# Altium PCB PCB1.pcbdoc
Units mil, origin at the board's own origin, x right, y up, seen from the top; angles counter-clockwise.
Board outline 2818.05 x 1914.09 mil, 2 copper layers (Top Layer, Bottom Layer), stack 62.206 mil thick; 39 components, 24 nets, 192 pads, 30 vias.
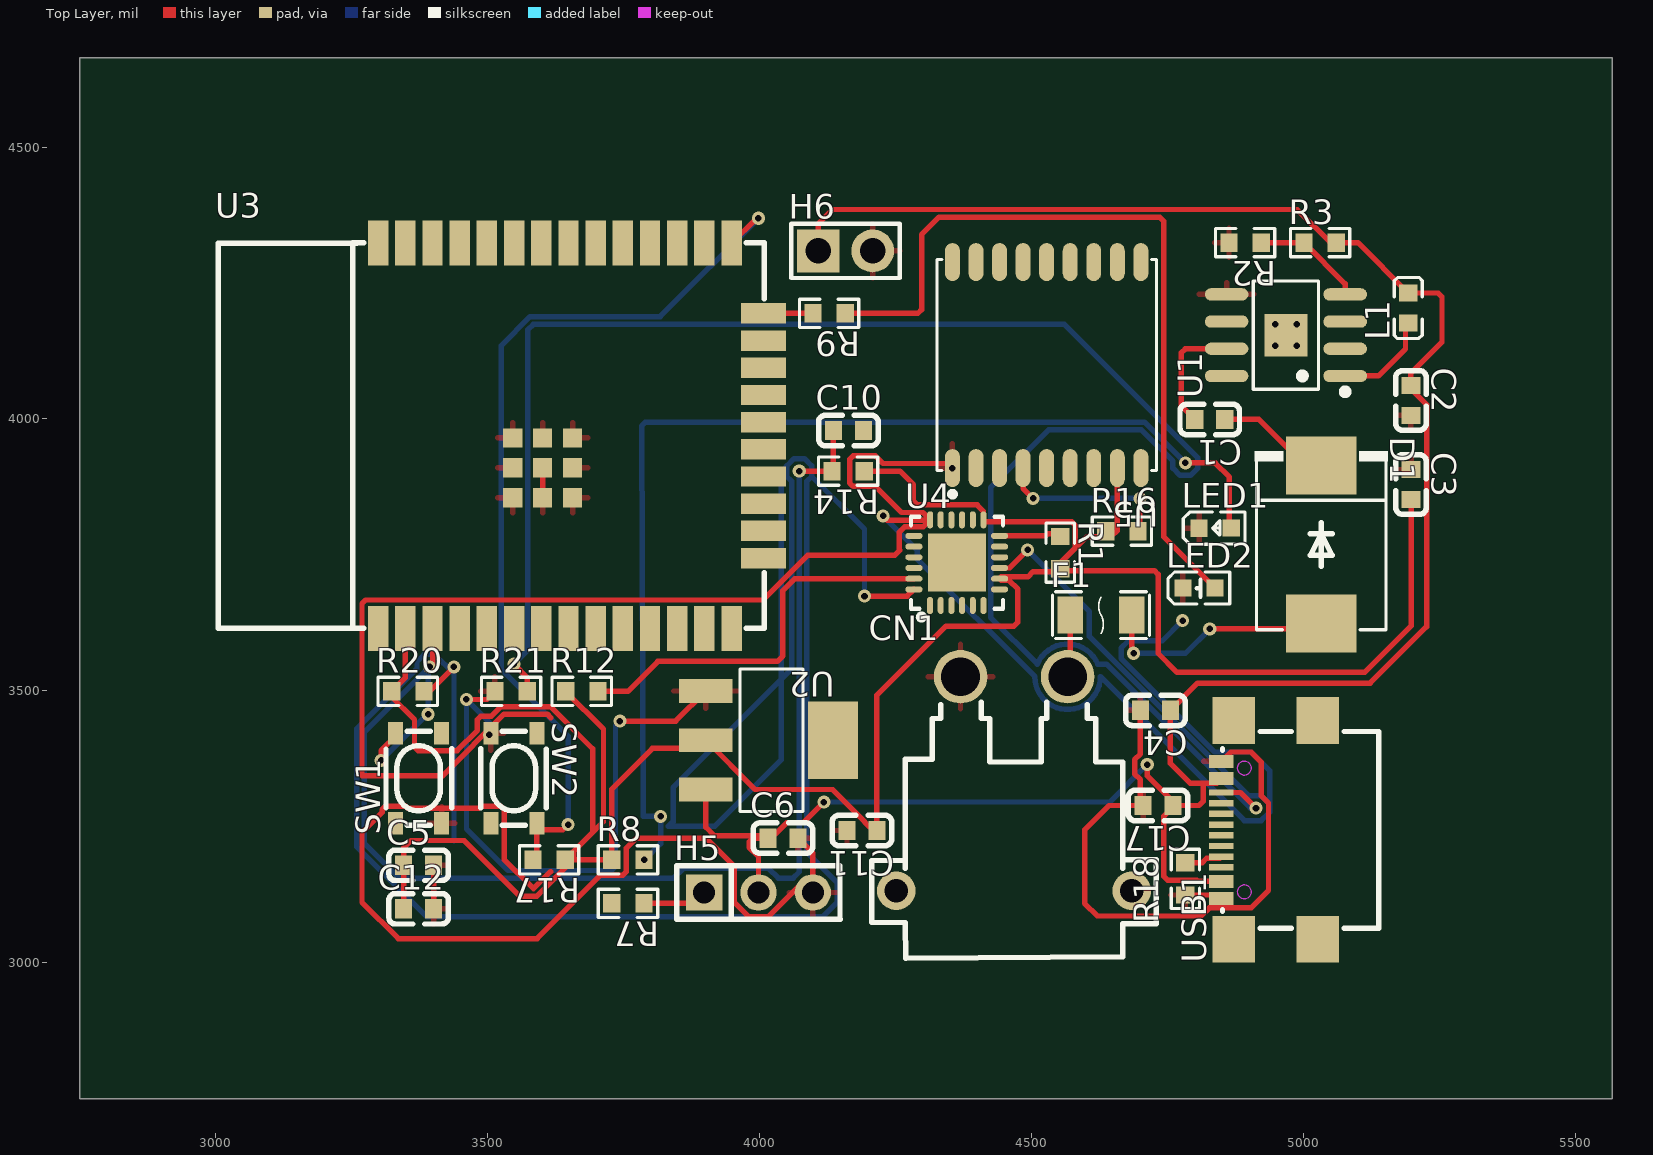
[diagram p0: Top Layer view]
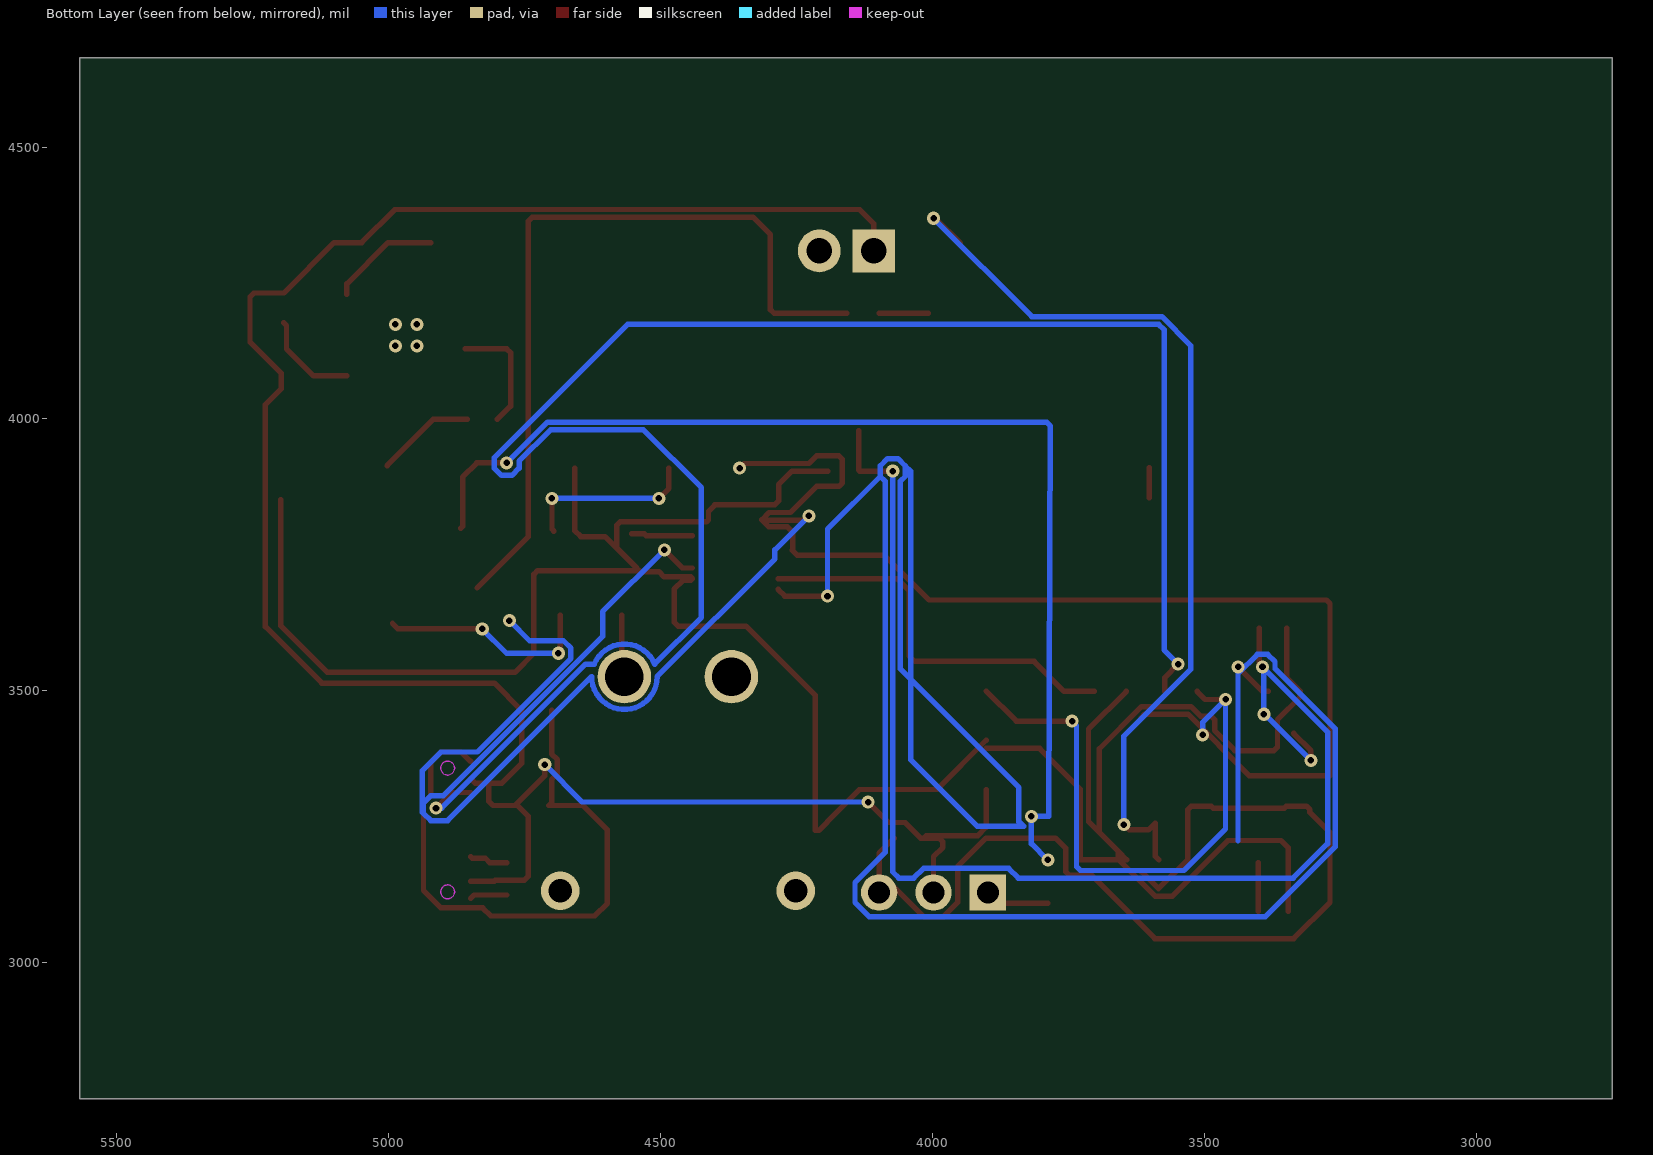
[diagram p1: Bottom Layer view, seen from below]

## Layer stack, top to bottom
Top Solder Mask Layer: solder mask 0.394, Dk 3.3
Top Layer: signal copper 1.379
Dielectric1: surface 59.449, FR4, Dk 4.5
Bottom Layer: signal copper 1.378
Bottom Solder Mask Layer: solder mask 0.394, Dk 3.3

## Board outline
5568.05,2750 2750,2750 2750,4664.09 5568.05,4664.09

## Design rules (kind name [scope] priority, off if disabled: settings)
BoardOutlineClearance copperThickness1oz [All] p0: genericclearance=10 ignorepadtopadclearanceinfootprint=FALSE except(0: Arc-SplitContinuation Track-SplitContinuation SMDPad-SplitContinuation THPad-SplitContinuation Via-SplitContinuation Fill-SplitContinuation Poly-SplitContinuation Region-SplitContinuation Text-SplitContinuation)
BoardOutlineClearance copperThickness2oz [All] p0: genericclearance=10 ignorepadtopadclearanceinfootprint=FALSE except(0: Arc-SplitContinuation Track-SplitContinuation SMDPad-SplitContinuation THPad-SplitContinuation Via-SplitContinuation Fill-SplitContinuation Poly-SplitContinuation Region-SplitContinuation Text-SplitContinuation)
BoardOutlineClearance otherClearance [All] p0: genericclearance=10 ignorepadtopadclearanceinfootprint=FALSE except(0: Arc-SplitContinuation Track-SplitContinuation SMDPad-SplitContinuation THPad-SplitContinuation Via-SplitContinuation Fill-SplitContinuation Poly-SplitContinuation Region-SplitContinuation Text-SplitContinuation)
Clearance copperThickness1oz [All] p1: gap=7 ignorepadtopadclearanceinfootprint=FALSE
Clearance copperThickness2oz [All] p1: gap=7 ignorepadtopadclearanceinfootprint=FALSE
Clearance otherClearance [All] p1: gap=7 ignorepadtopadclearanceinfootprint=FALSE
DiffPairsRouting differentialPair [All] p1: maxuncoupledlength=10 minlimit=6 maxlimit=Infinity mostfreqgap=6 toplayer_minwidth=5 toplayer_prefwidth=10 toplayer_maxwidth=100 bottomlayer_minwidth=5 bottomlayer_prefwidth=10 bottomlayer_maxwidth=100
PasteMaskExpansion pasteMaskExpansion [All] p1: expansion=0
PlaneConnect innerPlane [All] p1: planeconnectstyle=Relief reliefexpansion=20 reliefentries=4 reliefconductorwidth=10 reliefairgap=10
PolygonConnect copperRegion [All] p1: connectstyle=Relief reliefentries=4 reliefconductorwidth=10 polygonreliefangle="90 Angle" airgapwidth=10
RoutingVias viaSize [All] p1: viastyle="Through Hole" holewidth=12.0078 minholewidth=11.811 maxholewidth=248.0314 width=12.0078 minwidth=11.811 maxwidth=248.0314
SolderMaskExpansion solderMaskExpansion [All] p1: useseparateexpansions=TRUE expansion=2 expansionbottom=2
Width copperThickness1oz [All] p1: maxlimit=100 minlimit=5 preferedwidth=10
Width copperThickness2oz [All] p1: maxlimit=100 minlimit=8 preferedwidth=10

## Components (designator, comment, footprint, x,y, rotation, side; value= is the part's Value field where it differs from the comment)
C1 "" C0603 4828.05,3999.09 r180 top
C2 "" C0603 5198.05,4034.09 r270 top
C3 "" C0603 5198.27,3879.34 r270 top
C4 "" C0603 4728.05,3464.09 r180 top
C5 "" C0603 3373.05,3179.09 r0 top
C6 "" C0603 4043.05,3229.09 r0 top
C10 "" C0603 4163.4,3978.74 r0 top
C11 "" C0603 4188.4,3243.15 r180 top
C12 "" C0603 3373.05,3099.09 r0 top
C17 "" C0603 4733.05,3289.09 r180 top
CN1 "" CONN-TH_XT30PW-M 4468.05,3329.09 r0 top
D1 "" SMC_L6.9-W5.9-LS7.9-RD 5033.05,3769.09 r270 top
F1 "" F1206 4628.05,3639.09 r0 top
H5 "" HDR-TH_3P-P2.54-V-M_PZ254V-11-03P 3998.05,3129.09 r0 top
H6 "" HDR-TH_2P-P2.54-V-M 4158.05,4309.09 r0 top
L1 "" L0603 5193.05,4204.09 r90 top
LED1 "" LED0603-RD_RED 4838.05,3799.09 r0 top
LED2 "" LED0603-R-RD 4808.05,3689.09 r0 top
R1 "" R0603 4553.05,3754.09 r270 top
R2 "" R0603 4893.05,4324.09 r180 top
R3 "" R0603 5030.97,4324.34 r0 top
R7 "" R0603 3758.05,3109.09 r180 top
R8 "" R0603 3758.05,3189.09 r0 top
R9 "" R0603 4128.05,4194.09 r180 top
R12 "" R0603 3673.05,3499.09 r0 top
R14 "" R0603 4163.05,3904.09 r180 top
R16 "" R0603 4666.46,3793.51 r0 top
R17 "" R0603 3613.05,3189.09 r180 top
R18 "" R0603 4783.05,3154.09 r90 top
R20 "" R0603 3353.05,3499.09 r0 top
R21 "" R0603 3543.05,3499.09 r0 top
SW1 "" KEY-SMD_4P-L4.2-W3.2-P2.20-LS4.6 3373.05,3339.09 r90 top
SW2 "" KEY-SMD_4P-L4.2-W3.2-P2.20-LS4.6 3548.05,3339.09 r270 top
U1 "" SOIC-8_L5.0-W4.0-P1.27-LS6.0-BL-EP2.0 4968.05,4154.09 r90 top
U2 "" SOT-223-3_L6.5-W3.4-P2.30-LS7.0-BR 4018.05,3409.09 r180 top
U3 "" WIFI-SMD_ESP32-WROOM-32E 3653.05,3969.09 r0 top
U4 "" QFN-24_L4.0-W4.0-P0.50-BL-EP2.7 4362.72,3735.73 r0 top
U5 "" GPSM-SMD_ATGM336H-TR 4528.05,4099.09 r180 top
USB1 "" USB-C-SMD_TYPE-C-16P-USB4110-GF-A 4938.05,3244.09 r90 top

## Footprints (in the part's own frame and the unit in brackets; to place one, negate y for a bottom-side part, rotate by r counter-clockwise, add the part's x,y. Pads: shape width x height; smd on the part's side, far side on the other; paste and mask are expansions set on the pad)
C0603 [mm]
  rect 0.8x0.9 smd: 1(-0.7,0) 2(0.7,0)
  silkscreen extent -1.39,-0.71 1.39,0.71
CONN-TH_XT30PW-M [mm]
  round 2.5 hole 1.8: 1(-2.5,5) 2(2.5,5)
  round 1.8 hole 1.1: 3(5.5,-5) 4(-5.5,-5)
  silkscreen extent -6.65,-8.15 6.65,3.81
F1206 [mm]
  rect 1.19x1.728 smd: 1(-1.445,0) 2(1.445,0)
  silkscreen extent -2.27,-1.09 2.27,1.09
GPSM-SMD_ATGM336H-TR [mm]
  oval 0.7x1.773 smd: 1(4.4,4.811) 2(3.3,4.811) 3(2.2,4.811) 4(1.1,4.811) 5(0,4.811) 6(-1.1,4.811) 7(-2.2,4.811) 8(-3.3,4.811) 9(-4.4,4.811) 10(-4.4,-4.812) 11(-3.3,-4.812) 12(-2.2,-4.812) 13(-1.1,-4.812) 14(0,-4.812) 15(1.1,-4.812) 16(2.2,-4.812) 17(3.3,-4.812) 18(4.4,-4.812)
  silkscreen extent -5.13,-4.93 5.13,6.15
HDR-TH_2P-P2.54-V-M [mm]
  rect 2x2 hole 1.2: 1(-1.27,0)
  round 2 hole 1.2: 2(1.27,0)
  silkscreen extent -2.54,-1.27 2.54,1.27
HDR-TH_3P-P2.54-V-M_PZ254V-11-03P [mm]
  rect 1.7x1.7 hole 1.02: 1(-2.54,0)
  round 1.7 hole 1.02: 2(0,0) 3(2.54,0)
  silkscreen extent -3.81,-1.25 3.81,1.25
KEY-SMD_4P-L4.2-W3.2-P2.20-LS4.6 [mm]
  rect 1.05x0.7 smd: 1(-2.1,1.075) 2(2.1,1.075) 3(-2.1,-1.075) 4(2.1,-1.075)
  silkscreen extent -2.2,-1.55 2.2,1.52
L0603 [mm]
  rect 0.8x0.864 smd: 1(-0.7,0) 2(0.7,0)
  silkscreen extent -1.42,-0.65 1.42,0.65
LED0603-R-RD [mm]
  rect 0.8x0.8 smd: 1(0.751,0) 2(-0.751,0)
  silkscreen extent -1.44,-0.75 1.44,0.75
LED0603-RD_RED [mm]
  rect 0.8x0.8 smd: 1(-0.749,-0.003) 2(0.749,0.003)
  silkscreen extent -1.49,-0.75 1.39,0.76
QFN-24_L4.0-W4.0-P0.50-BL-EP2.7 [mm]
  oval 0.28x0.8 smd: 1(-1.25,-2) 2(-0.75,-2) 3(-0.25,-2) 4(0.25,-2) 5(0.75,-2) 6(1.25,-2) 13(1.25,2) 14(0.75,2) 15(0.25,2) 16(-0.25,2) 17(-0.75,2) 18(-1.242,2)
  oval 0.8x0.28 smd: 7(2,-1.25) 8(2,-0.75) 9(2,-0.25) 10(2,0.25) 11(2,0.75) 12(2,1.25) 19(-2,1.25) 20(-2,0.75) 21(-2,0.25) 22(-2,-0.25) 23(-2,-0.75) 24(-2,-1.25)
  rect 2.7x2.7 smd: 25(0.012,0)
  silkscreen extent -2.14,-2.79 2.16,2.15
R0603 [mil]
  rect 31.75x34.02 smd: 1(-29.66,0) 2(29.66,0)
  silkscreen extent -55,-26 55,26
SMC_L6.9-W5.9-LS7.9-RD [mm]
  rect 2.7x3.3 smd: 1(-3.686,0) 2(3.686,0)
  silkscreen extent -4.36,-3.1 3.98,3.1
SOIC-8_L5.0-W4.0-P1.27-LS6.0-BL-EP2.0 [mm]
  oval 0.574x2.038 smd: 1(-1.905,-2.769) 2(-0.635,-2.769) 3(0.635,-2.769) 4(1.905,-2.769) 5(1.905,2.769) 6(0.635,2.769) 7(-0.635,2.769) 8(-1.905,2.769)
  rect 2x2 smd: 9(0,0)
  silkscreen extent -2.79,-2.92 2.53,1.52
SOT-223-3_L6.5-W3.4-P2.30-LS7.0-BR [mm]
  rect 2.5x1.1 smd: 1(2.97,-2.3) 2(2.97,0) 3(2.97,2.3)
  rect 2.34x3.6 smd: 4(-2.97,0)
  silkscreen extent -1.57,-3.33 1.37,3.33
USB-C-SMD_TYPE-C-16P-USB4110-GF-A [mm]
  rect 2.18x2 smd: 8(-5.11,1.677) 9(5.11,1.677) 10(-5.11,-2.252) 11(5.11,-2.252)
  rect 0.6x1.15 smd: A1B12(-3.2,2.252) A4B9(-2.4,2.252) B1A12(3.2,2.252) B4A9(2.4,2.252)
  rect 0.3x1.15 smd: A5(-1.25,2.252) A6(-0.25,2.252) A7(0.25,2.252) A8(1.25,2.252) B5(1.75,2.252) B6(0.75,2.252) B7(-0.75,2.252) B8(-1.75,2.252)
  Board Outline Layer circle w0.003: c2.89,1.177 r0.325
  Board Outline Layer circle w0.003: c-2.89,1.177 r0.325
  Board Outline Layer region: 2.89,0.853 2.749,0.885 2.636,0.975 2.573,1.105 2.573,1.25 2.636,1.38 2.749,1.47 2.89,1.502 2.89,1.502 3.031,1.47 3.144,1.38 3.207,1.25 3.207,1.105 3.144,0.975 3.031,0.885 2.89,0.853
  Board Outline Layer region: 2.89,0.853 2.749,0.885 2.636,0.975 2.573,1.105 2.573,1.25 2.636,1.38 2.749,1.47 2.89,1.502 2.89,1.502 3.031,1.47 3.144,1.38 3.207,1.25 3.207,1.105 3.144,0.975 3.031,0.885 2.89,0.853
  Board Outline Layer region: -2.89,0.853 -3.031,0.885 -3.144,0.975 -3.207,1.105 -3.207,1.25 -3.144,1.38 -3.031,1.47 -2.89,1.502 -2.89,1.502 -2.749,1.47 -2.636,1.38 -2.573,1.25 -2.573,1.105 -2.636,0.975 -2.749,0.885 -2.89,0.853
  Board Outline Layer region: -2.89,0.853 -3.031,0.885 -3.144,0.975 -3.207,1.105 -3.207,1.25 -3.144,1.38 -3.031,1.47 -2.89,1.502 -2.89,1.502 -2.749,1.47 -2.636,1.38 -2.573,1.25 -2.573,1.105 -2.636,0.975 -2.749,0.885 -2.89,0.853
  silkscreen extent -4.6,-5.1 4.6,2.2
WIFI-SMD_ESP32-WROOM-32E [mm]
  rect 0.95x2.1 smd: 1(-9.003,-9) 2(-7.733,-9) 3(-6.463,-9) 4(-5.193,-9) 5(-3.923,-9) 6(-2.653,-9) 7(-1.383,-9) 8(-0.113,-9) 9(1.157,-9) 10(2.427,-9) 11(3.697,-9) 12(4.967,-9) 13(6.237,-9) 14(7.507,-9) 25(7.507,9) 26(6.237,9) 27(4.967,9) 28(3.697,9) 29(2.427,9) 30(1.157,9) 31(-0.113,9) 32(-1.383,9) 33(-2.653,9) 34(-3.923,9) 35(-5.193,9) 36(-6.463,9) 37(-7.733,9) 38(-9.003,9)
  rect 2.1x0.95 smd: 15(9.003,-5.715) 16(9.003,-4.445) 17(9.003,-3.175) 18(9.003,-1.905) 19(9.003,-0.635) 20(9.003,0.635) 21(9.003,1.905) 22(9.003,3.175) 23(9.003,4.445) 24(9.003,5.715)
  rect 0.9x0.9 smd: 39(-2.722,-2.9) 39(-2.722,-1.5) 39(-2.722,-0.1) 39(-1.322,-2.9) 39(-1.322,-1.5) 39(-1.322,-0.1) 39(0.078,-2.9) 39(0.078,-1.5) 39(0.078,-0.1)
  silkscreen extent -16.48,-9 9.02,9.02

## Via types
v1: diameter 24.02, hole 12.01, Top Layer to Bottom Layer, 26 vias
v2: diameter 24, hole 12, Top Layer to Bottom Layer, 4 vias

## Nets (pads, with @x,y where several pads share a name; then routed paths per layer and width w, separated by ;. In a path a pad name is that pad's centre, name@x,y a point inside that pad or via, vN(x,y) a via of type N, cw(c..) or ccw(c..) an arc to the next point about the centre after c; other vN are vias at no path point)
3.3V: C3.2 C5.1 C11.1 C12.1 R1.2 R8.1 R12.1 R14.1 R16.1 R17.1 R20.1 U2.2 U3.2 U4.8 U4.13 U5.8 | length 5167.4
  Top Layer w10: C12.1@3345.49,3094.09 3345.49,3211.19 3359.06,3224.76 3456.57,3224.76 3559.31,3122.02 3590.16,3122.02 R17.1@3657.23,3189.09 ; U3.2 3348.62,3524.32 R20.1 3323.39,3489.1 3365.49,3446.99 3365.49,3396.56 3371.93,3390.12 3443.7,3390.12 3480.97,3427.39 3480.97,3446.99 3487.4,3453.43 3507.01,3453.43 3524.68,3471.1 3615.42,3471.1 3693.05,3393.47 3693.05,3239.43 ; R12.1 3713.05,3429.43 3713.05,3259.43 3693.05,3239.43 ; U2.2@3901.12,3394.09 3803.05,3394.09 3728.39,3319.43 R8.1 R17.1@3657.23,3189.09 ; U2.2 3991.75,3318.47 4134.51,3318.47 4193.05,3259.93 4193.05,3259.09 4209,3243.15 C11.1 4215.96,3492 4343.05,3619.09 4468.05,3619.09 4475.12,3626.17 4475.12,3687.02 4459.13,3703.02 4444.64,3703.02 U4.8 4444.65,3709.39 4493.35,3709.39 4503.01,3719.06 4536.77,3719.06 4538.88,3721.17 4725.98,3721.17 4733.05,3714.09 4733.05,3569.09 4768.05,3534.09 5113.05,3534.09 5198.27,3619.32 C3.2 ; R14.1 4258.05,3904.09 4283.05,3879.09 4283.05,3849.09 4290.12,3842.02 4400.12,3842.02 4411.93,3830.22 U4.13 4415.79,3810.61 4574.61,3810.61 4581.04,3804.18 4581.04,3763.33 4543.51,3725.8 4544.75,3725.8 4602.47,3783.51 4646.8,3783.51 4657.97,3794.68 U5.8 ; R17.1@3657.23,3189.09 3658.05,3189.92 R17.1@3658.05,3204.43 ; R17.1@3657.23,3189.09 R17.1 R17.1@3658.05,3204.43 ; R17.1@3658.05,3204.43 3693.05,3239.43
$1N2: CN1.2 F1.1 | length 115.1
  Top Layer w10: CN1.2 4571.16,3530.63 F1.1
$1N4: D1.2 F1.2 | length 399
  Top Layer w10: F1.2 4684.94,3572.2 v1(4688.05,3569.09) ; v1(4828.05,3614.09) 4983.18,3614.09 D1.2@4993.05,3623.96
  Bottom Layer w10: v1(4688.05,3569.09) 4783.05,3569.09 v1(4828.05,3614.09)
$1N7: L1.1 U1.1 | length 181.2
  Top Layer w10: U1.1 5138.05,4079.09 5188.05,4129.09 5188.05,4171.54 L1.1
$1N19: R17.2 SW2.2 U3.25 | length 1707.3
  Top Layer w10: R17.2 3590.37,3196.07 SW2.2 3602.69,3244.09 3638.05,3244.09 v1(3648.05,3254.09) ; U3.25 3994.29,4369.09 v1(3998.05,4369.09)
  Bottom Layer w10: v1(3648.05,3254.09) 3648.05,3416.58 3525.06,3539.57 3525.06,4134.94 3578.23,4188.11 3817.07,4188.11 v1(3998.05,4369.09)
$1N22: C10.1 R14.2 SW1.2 U3.3 | length 2435
  Top Layer w10: v1(3304.03,3371.98) 3304.03,3390.08 SW1.2@3335.73,3421.77 ; v1(3393.05,3544.09) 3398.62,3549.66 U3.3 ; v1(4073.05,3904.09) R14.2 4135.84,3906.54 C10.1
  Bottom Layer w10: v1(3304.03,3371.98) 3389,3456.94 v1(3390.64,3456.94) 3390.64,3537.38 v1@3388.49,3539.53 ; v1(3393.05,3544.09) v1@3388.49,3539.53 ; v1(4073.05,3904.09) 4073.05,3166.95 4061.62,3155.52 4034.48,3155.52 4016.46,3173.54 3860.04,3173.54 3842.02,3155.52 3336.62,3155.52 3273.05,3219.09 3273.05,3424.09 v1@3388.49,3539.53
$1N25: LED1.2 R8.2 | length 2063.2
  Top Layer w10: v1(4783.05,3919.09) 4838.05,3919.09 4864.03,3893.11 4864.03,3802.74 LED1.2
  Bottom Layer w10: v1@3788.05,3189.09 3818.05,3219.09 v1(3818.05,3269.09) 3786.33,3269.09 3783.05,3987.02 3790.12,3994.09 4708.05,3994.09 v1(4783.05,3919.09)
  other v1: 3787.71,3189.09
$1N27: R9.2 U3.24 | length 90.9
  Top Layer w10: U3.24 R9.2
$1N28: LED2.1 R9.1 | length 1456.6
  Top Layer w10: R9.1 4290.98,4194.09 4298.05,4201.17 4298.05,4339.09 4330.12,4371.17 4735.98,4371.17 4743.05,4364.09 4743.05,3783.66 LED2.1
$1N34: C1.1 D1.1 | length 182.6
  Top Layer w10: C1.1 4918.18,3999.09 D1.1@5003.05,3914.22
$1N35: C1.2 U1.7 | length 219.1
  Top Layer w10: C1.2 4775.98,4023.61 4775.98,4122.02 4783.05,4129.09 U1.7
$1N40: R2.1 R3.1 U1.4 | length 205.3
  Top Layer w10: R2.1 5001.06,4324.09 R3.1 5077.07,4248.58 U1.4
$1N51: R18.2 USB1.A5 | length 70.9
  Top Layer w10: R18.2 4813.85,3183.75 4822.18,3192.08 4846.57,3192.08 USB1.A5
$1N56: R21.2 USB1.B5 | length 3493.7
  Top Layer w10: v1(3548.05,3549.09) 3572.71,3524.43 R21.2 ; USB1.B5 4884.15,3312.99 v1(4913.05,3284.09)
  Bottom Layer w10: v1(3548.05,3549.09) 3574.04,3575.08 3574.04,4164.09 3584.04,4174.09 4560.57,4174.09 4806.04,3928.62 4806.04,3909.57 4792.57,3896.1 4773.53,3896.1 4760.06,3909.57 4760.06,3922.27 4702.25,3980.08 4531.55,3980.08 4425.19,3873.72 4425.19,3634.81 4510.91,3549.09 cw(c4566.48,3525.94) 4622.04,3549.09 4637.87,3549.09 4902.87,3284.09 v1(4913.05,3284.09)
$1N92: H5.1 R7.1 | length 118.6
  Top Layer w10: R7.1 3878.05,3109.09 H5.1
+5V: C2.1 C4.1 C6.1 C17.1 H5.2 H6.1 L1.2 R3.2 U2.3 USB1.A4B9 USB1.B4A9 | length 4181.4
  Top Layer w10: U2.3 3901.12,3249.09 3917.09,3233.13 4011.45,3233.13 C6.1 ; H5.2 3998.05,3194.95 3980.98,3212.02 3980.98,3222.02 3988.05,3229.09 C6.1 ; H6.1 4108.05,4359.09 4134.14,4385.18 4988.88,4385.18 5049.72,4324.34 R3.2 5100.36,4324.34 L1.2 5248.05,4231.65 5255.12,4224.58 5255.12,4141.17 5198.05,4084.09 C2.1 5198.05,4055.53 5226.98,4026.61 5226.98,3618.02 5123.05,3514.09 4805.61,3514.09 C4.1 4755.61,3366.53 4792.26,3329.88 4818.84,3329.88 ; v1(4118.2,3295.48) 4080.52,3257.8 4050.31,3257.8 4021.61,3229.09 C6.1 ; v1(4713.05,3364.09) 4713.05,3344.09 C17.1@4768.05,3289.09 ; USB1.A4B9 4806.3,3149.61 4804.61,3151.29 4750.85,3151.29 4743.05,3159.09 4743.05,3269.09 4763.05,3289.09 C17.1@4768.05,3289.09 ; USB1.B4A9 4840.67,3329.88 4818.84,3329.88 ; C17.1@4768.05,3289.09 4808.05,3289.09 4815.75,3296.79 4815.75,3326.79 4818.84,3329.88
  Bottom Layer w10: v1(4118.2,3295.48) 4644.44,3295.48 v1(4713.05,3364.09)
GND: C2.2 C3.1 C4.2 C5.2 C6.2 C11.2 C12.2 C17.2 CN1.1 H5.3 H6.2 LED1.1 LED2.2 R2.2 R18.1 R21.1 SW1.3 SW2.3 U1.5 U2.1 U3.39 U4.9 U4.18 U5.1 USB1.A1B12 USB1.B1A12 | length 9001.2
  Top Layer w10: C12.2@3400.61,3094.09 C5.2@3400.61,3184.09 ; v1(3461.04,3484.09) 3498.39,3484.09 R21.1 ; U3.39@3601.02,3854.92 U3.39@3601.02,3910.03 ; 3615.85,3167.54 3584.35,3136.04 3530.49,3189.9 3530.49,3281.63 3524.06,3288.07 3487.4,3288.07 3483.43,3284.09 3353.03,3284.09 3349.06,3288.07 3312.4,3288.07 3305.97,3281.63 3305.97,3276.63 3268.94,3239.6 3268.94,3110.88 3335.72,3044.09 3590.96,3044.09 3707.97,3161.1 3748.82,3161.1 3755.25,3167.54 3755.25,3210.65 3773.69,3229.09 3901.3,3229.09 3953.6,3176.8 3953.6,3110.68 3979.64,3084.65 4016.46,3084.65 H5.3@4070.61,3138.79 ; 3615.85,3450.85 3609.61,3457.09 3530.49,3457.09 3417.5,3344.09 3268.94,3344.09 3268.94,3660.65 3275.37,3667.08 4006.22,3667.08 4088.23,3749.09 4248.44,3749.09 4257.51,3758.16 4257.25,3758.43 4257.25,3791.77 4266.91,3801.44 4300.79,3801.44 U4.18 4300.28,3828.01 4261.23,3828.01 4213.14,3876.1 4172.29,3876.1 4165.85,3882.54 4165.85,3925.65 4172.29,3932.09 4213.14,3932.09 4227.11,3918.11 4346.38,3918.11 v1(4354.82,3909.67) ; v1(3743.05,3444.09) 3845.57,3444.09 U2.1 ; C6.2 4098.05,3201.65 H5.3 ; v1(4227.11,3821.72) 4234.74,3814.09 4308.05,3814.09 ; U4.9 4459.85,3725.89 v1(4493.05,3759.09) ; C4.2 4700.49,3384.05 4690.06,3373.62 4690.06,3347.27 4700.49,3336.83 4700.49,3294.09 C17.2 4643.05,3289.09 4598.05,3244.09 4598.05,3109.09 4621.32,3085.83 4812.34,3085.83 4827.22,3100.71 4903.96,3100.71 4936.04,3132.8 4936.04,3293.62 4922.57,3307.09 4922.57,3368.86 4903.96,3387.48 4866.77,3387.48 USB1.B1A12 ; R18.1 4843.05,3124.43 USB1.A1B12
  Bottom Layer w10: v1(3503.05,3419.09) 3503.05,3442.09 v1(3461.04,3484.09) 3461.04,3246.1 3537.61,3169.54 3728.05,3169.54 3735.12,3176.61 3735.12,3436.17 v1(3743.05,3444.09) ; v1(4227.11,3821.72) 4289.74,3759.09 4289.74,3742.49 4506.28,3525.94 ccw(c4566.48,3525.94) 4626.67,3525.94 4891.52,3261.1 4922.57,3261.1 4936.04,3274.57 ; v1(4493.05,3759.09) 4606.63,3645.51 4606.63,3600.16 4899.7,3307.09 4922.57,3307.09 4936.04,3293.62 4936.04,3274.57 ; v1(4778.05,3629.09) 4741.04,3592.09 4678.53,3592.09 4665.06,3578.62 4665.06,3559.57 4837.15,3387.48 4903.96,3387.48 4938.05,3353.39 4938.05,3276.58 4936.04,3274.57
IO16: U5.2
IO17: U5.3
IO21: R20.2 U4.24 | length 4623.6
  Top Layer w10: R20.2 3393.05,3499.09 v1(3438.05,3544.09) ; v1(4193.05,3674.09) 4271.55,3674.09 U4.24
  Bottom Layer w10: 3438.05,3224.09 3438.05,3531.61 ; v1(3438.05,3544.09) 3438.05,3531.61 ; v1(4193.05,3674.09) 4193.05,3797.56 4096.04,3894.57 ; 3438.05,3531.61 3402.57,3567.09 3383.53,3567.09 3370.06,3553.62 3370.06,3540.92 3259.04,3429.9 3259.04,3213.29 3387.68,3084.65 4116.46,3084.65 4142.5,3110.68 4142.5,3147.51 4087.07,3202.94 4087.07,3885.59 4096.04,3894.57 ; 4040.29,3521.33 4040.29,3903.85 4050.06,3913.62 ; 4040.29,3521.33 4040.29,3373.61 3917.27,3250.59 3832.07,3250.59 3841.04,3259.57 3841.04,3322.09 4040.29,3521.33 ; 4040.29,3521.33 4059.04,3540.08 4059.04,3885.59 4050.06,3894.57 4050.06,3913.62 ; 4050.06,3913.62 4063.53,3927.09 4082.57,3927.09 4096.04,3913.62 4096.04,3894.57
IO22: R12.2 U4.23 | length 737.4
  Top Layer w10: R12.2 3758.05,3499.09 3813.05,3554.09 4033.05,3554.09 4043.05,3564.09 4043.05,3684.09 4065.16,3706.2 U4.23
IO25: R7.2
IO34: R1.1 U4.12 | length 113.2
  Top Layer w10: U4.12 4526.29,3784.94 4530.1,3788.75 R1.1@4553.05,3788.75
IO35: R16.2 U5.4 | length 322
  Top Layer w10: U5.4 4484.74,3872.41 v1(4503.05,3854.09) ; R16.2 4699.77,3797.16 v1(4699.77,3854.09)
  Bottom Layer w10: v1(4503.05,3854.09) v1(4699.77,3854.09)
pads on no net: C10.2 CN1.3 CN1.4 SW1.1 SW1.4 SW2.1 SW2.4 U1.2 U1.3 U1.6 U1.8 U1.9 U2.4 U3.1 U3.4 U3.5 U3.6 U3.7 U3.8 U3.9 U3.10 U3.11 U3.12 U3.13 U3.14 U3.15 U3.16 U3.17 U3.18 U3.19 U3.20 U3.21 U3.22 U3.23 U3.26 U3.27 U3.28 U3.29 U3.30 U3.31 U3.32 U3.33 U3.34 U3.35 U3.36 U3.37 U3.38 U4.1 U4.2 U4.3 U4.4 U4.5 U4.6 U4.7 U4.10 U4.11 U4.14 U4.15 U4.16 U4.17 U4.19 U4.20 U4.21 U4.22 U4.25 U5.5 U5.6 U5.7 U5.9 U5.10 U5.11 U5.12 U5.13 U5.14 U5.15 U5.16 U5.17 U5.18 USB1.8 USB1.9 USB1.10 USB1.11 USB1.A6 USB1.A7 USB1.A8 USB1.B6 USB1.B7 USB1.B8
copper on no net:
  other v2: 4948.37,4134.41 4987.74,4134.41 4948.37,4173.78 4987.74,4173.78

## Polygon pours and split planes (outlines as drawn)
GND on Top Layer (solid, remove dead copper, pour order 0): 3248.05,4414.09 5318.05,4414.09 5318.05,3024.09 3248.05,3024.09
